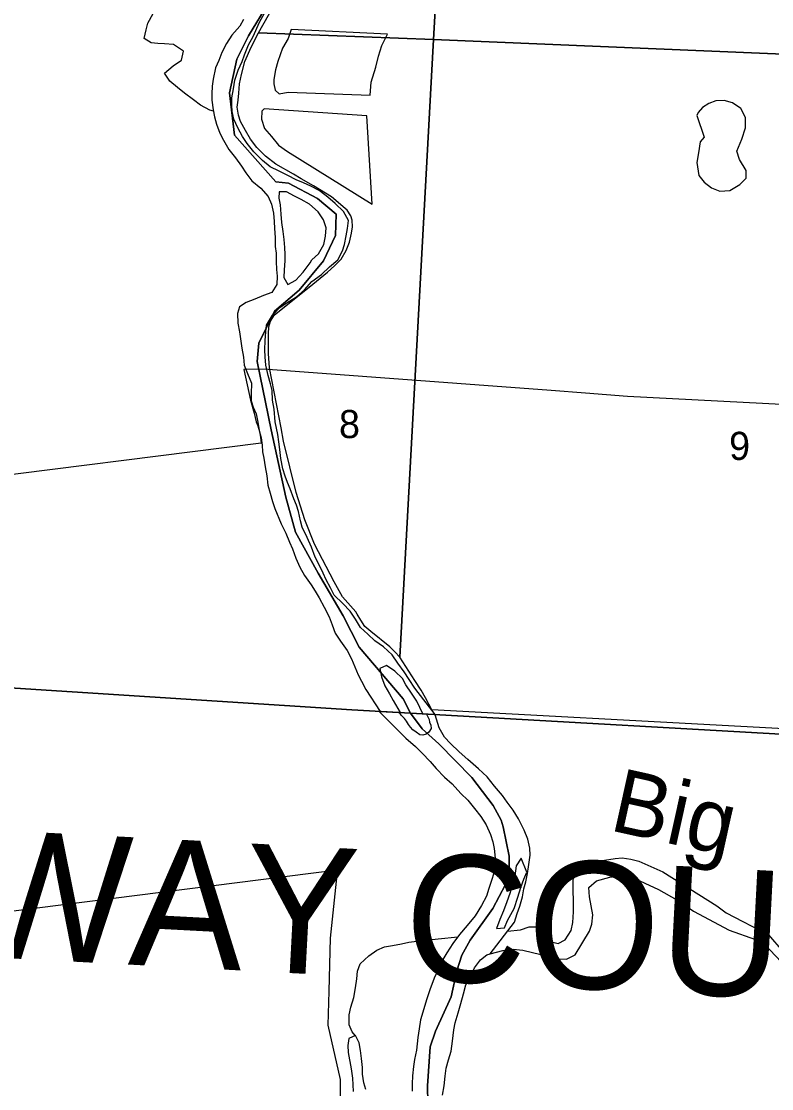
# Model space of a CAD drawing. Extents: x 114843 to 284848, y 317643 to 566895.
# Drawn here: x 199714 to 205606, y 326386 to 334768 of the extents above; entities that cross this region are included whole.
import ezdxf

# ---------------------------------------------------------------- set-up
doc = ezdxf.new("R2010")
doc.units = 0
for name, color, linetype in [('GM_X_Corporation', 7, 'Continuous'), ('GM_X_County', 7, 'Continuous'), ('GM_X_County_Text', 7, 'Continuous'), ('GM_X_Major_River', 7, 'Continuous'), ('GM_X_Major_River_Text', 7, 'Continuous'), ('GM_X_Minor_Lake', 7, 'Continuous'), ('GM_X_Minor_River', 7, 'Continuous'), ('GM_X_Section', 7, 'Continuous'), ('GM_X_Section_Text', 7, 'Continuous'), ('GM_X_Township', 7, 'Continuous')]:
    doc.layers.add(name, color=color, linetype=linetype)

msp = doc.modelspace()

# ---------------------------------------------------------------- linework, layer by layer
at = {"layer": 'GM_X_Corporation'}
for points in [[(206644.7, 331708.2), (204474.5, 331822.7), (204143.4, 331847.9), (203874.5, 331868.4), (201650.8, 332033.4), (201477, 332036.8), (201459.8, 332033.6), (201514.5, 331793.1), (201542.2, 331690.1), (201549, 331656.5), (201558.7, 331623.7), (201571.1, 331591.7), (201584.4, 331547.6), (201592.9, 331502.4), (201596.7, 331456.5), (199148, 331145.7)], [(198057.5, 327582), (202194, 328104.1), (202192.1, 328065.1), (202137.8, 327567.4), (202127.6, 327150.8), (202119.3, 326884.1), (202218.1, 326458.1), (202215.1, 326147.7)]]:
    msp.add_lwpolyline(points, dxfattribs=at)
at = {"layer": 'GM_X_County'}
for points in [[(234341.9, 327550.6), (226717.6, 328003.9), (223790.5, 328228.4), (218560.3, 328475.9), (218545.2, 328479.5), (213224.9, 328764.7), (208151.1, 329070.4), (208095.2, 329072.5), (206186.9, 329142.4), (202769.6, 329336.1), (202309.8, 329362.2), (198524.2, 329604), (197723.9, 329650.3), (193707.8, 329789.4), (193407.6, 329798.8), (192869.2, 329809.1), (189197.4, 329916.7), (185190.3, 330011.9), (181070.3, 330252.9), (177726, 330436.1)], [(177726, 330436.1), (181070.3, 330252.9), (185190.3, 330011.9), (189197.4, 329916.7), (192869.2, 329809.1), (193407.6, 329798.8), (193707.8, 329789.4), (197723.9, 329650.3), (198524.2, 329604), (202309.8, 329362.2), (202769.6, 329336.1), (206186.9, 329142.4), (208095.2, 329072.5), (208151.1, 329070.4), (213224.9, 328764.7), (218545.2, 328479.5), (218560.3, 328475.9), (223790.5, 328228.4), (226717.6, 328003.9), (234341.9, 327550.6)]]:
    msp.add_lwpolyline(points, dxfattribs=at)
at = {"layer": 'GM_X_Major_River'}
for p, q in [((202684.1, 329340.1), (202523.2, 329348.3)), ((202531.3, 329348), (202964.2, 329323.3)), ((202689.8, 329339.9), (202866.6, 329330.1)), ((202963.4, 329323.2), (202894.9, 329326.6))]:
    msp.add_line(p, q, dxfattribs=at)
for points in [[(201458.7, 334782.7), (201428.7, 334730.5), (201366.8, 334660.2), (201324.9, 334594), (201289, 334523.8), (201265.1, 334459.6), (201239.1, 334403.4), (201221.3, 334313.1), (201213.4, 334259), (201209.5, 334198.8), (201209.5, 334148.7), (201219.7, 334072.5), (201229.8, 334018.4), (201245.9, 333960.3), (201272, 333890.2), (201300.1, 333834.1), (201344.3, 333762), (201396.4, 333695.9), (201442.6, 333631.9), (201476.7, 333577.8), (201524.8, 333515.8), (201595, 333457.8), (201653.1, 333393.7), (201677.2, 333331.6), (201693.4, 333261.5), (201699.5, 333195.3), (201701.6, 333141.2), (201705.7, 333071), (201707.8, 332998.8), (201713.9, 332948.7), (201716, 332882.6), (201718.1, 332818.4), (201722.2, 332766.3), (201720.3, 332702.1), (201680.4, 332637.9), (201616.4, 332615.7), (201548.4, 332585.5), (201480.4, 332561.3), (201426.4, 332525.1), (201410.5, 332474.9), (201412.6, 332398.7), (201426.7, 332330.6), (201434.8, 332274.5), (201444.9, 332200.3), (201457.1, 332130.2), (201463.2, 332068), (201489.3, 332001.9), (201521.5, 331925.8), (201519.6, 331843.6), (201519.7, 331787.4), (201533.8, 331737.3), (201557.9, 331685.2), (201572, 331621.1), (201582.1, 331555), (201596.2, 331496.9), (201604.3, 331440.7), (201608.4, 331388.6), (201618.5, 331338.5), (201628.6, 331270.4), (201640.7, 331198.2), (201648.9, 331126), (201669, 331063.9), (201685.1, 330997.8), (201705.2, 330941.7), (201753.4, 330821.5), (201789.6, 330747.4), (201819.7, 330677.3), (201843.8, 330625.2), (201870, 330551.1), (201900.1, 330480.9), (201938.2, 330416.9), (201990.4, 330342.8), (202020.5, 330292.7), (202052.6, 330240.7), (202090.8, 330168.6), (202130.9, 330092.5), (202155, 330028.3), (202177.2, 329962.2), (202221.3, 329900.2), (202273.5, 329826.1), (202305.6, 329762), (202331.7, 329699.9), (202359.8, 329635.8), (202383.9, 329585.7), (202418.1, 329519.6), (202531.3, 329348)], [(202804.3, 329532.4), (202760.2, 329600.5), (202720, 329660.6), (202669.9, 329726.6), (202625.8, 329792.7), (202557.6, 329856.7), (202489.5, 329902.7), (202435.4, 329956.7), (202377.2, 330008.7), (202337.1, 330072.8), (202297, 330134.9), (202238.8, 330196.9), (202170.7, 330262.9), (202140.5, 330319), (202108.4, 330381.1), (202084.3, 330435.2), (202058.2, 330489.3), (202022.1, 330561.4), (201991.9, 330639.5), (201957.8, 330715.6), (201919.6, 330795.8), (201905.5, 330845.9), (201889.4, 330918), (201873.3, 330968.1), (201853.2, 331018.2), (201825, 331096.3), (201802.9, 331146.4), (201784.8, 331196.5), (201766.7, 331254.6), (201752.6, 331334.8), (201744.5, 331406.9), (201736.4, 331467.1), (201728.3, 331523.2), (201718.2, 331573.3), (201708.1, 331623.4), (201699.9, 331723.6), (201685.8, 331793.8), (201683.7, 331870), (201669.6, 331922.1), (201651.4, 331986.2), (201633.3, 332068.4), (201629.2, 332132.5), (201627.1, 332188.7), (201629, 332262.8), (201634.9, 332329), (201638.8, 332383.2), (201686.7, 332459.4), (201742.6, 332519.7), (201806.6, 332563.9), (201874.6, 332604.2), (201936.5, 332660.4), (201994.5, 332724.7), (202070.4, 332781), (202132.4, 332839.3), (202198.3, 332895.6), (202236.2, 332965.8), (202250.2, 333016), (202264.1, 333084.2), (202276, 333140.3), (202281.9, 333204.5), (202243.7, 333274.6), (202177.6, 333336.6), (202119.5, 333386.6), (202051.3, 333438.6), (201987.2, 333472.6), (201929.1, 333500.5), (201873.1, 333524.5), (201807, 333558.4), (201738.8, 333592.4), (201668.7, 333624.3), (201606.6, 333674.3), (201540.5, 333744.3), (201486.3, 333808.4), (201450.2, 333864.5), (201414.1, 333930.6), (201381.9, 333998.7), (201369.8, 334060.8), (201365.7, 334112.9), (201367.6, 334167), (201379.5, 334239.2), (201389.4, 334305.4), (201417.3, 334385.7), (201447.2, 334453.9), (201465.1, 334506.1), (201497, 334584.3), (201532.9, 334648.5), (201584.8, 334760.9), (201622.7, 334831.2)], [(201739.1, 333430), (201735.2, 333379.8), (201745.3, 333327.7), (201751.4, 333253.6), (201757.5, 333187.4), (201767.7, 333117.3), (201775.8, 333055.1), (201779.9, 332991), (201782, 332936.8), (201782.1, 332886.7), (201778.2, 332816.5), (201776.3, 332756.4), (201806.4, 332702.3), (201870.4, 332734.5), (201926.3, 332798.8), (201982.2, 332871.1)], [(201982.2, 332871.1), (201996.2, 332895.1), (202048.1, 332943.4), (202088.1, 333015.6), (202101.9, 333081.8), (202107.8, 333146), (202087.7, 333210.1), (202045.6, 333272.2), (201975.4, 333332.2), (201911.3, 333370.2), (201859.3, 333394.1), (201797.2, 333428.1), (201739.1, 333430)], [(202866.6, 329330.1), (202820.5, 329428.2), (202778.4, 329492.3), (202734.2, 329558.3), (202708.1, 329608.4), (202648, 329664.4), (202581.9, 329708.4), (202529.9, 329686.3), (202542, 329620.1), (202568.1, 329550), (202604.3, 329487.9), (202634.4, 329433.9), (202689.8, 329339.9)], [(202964.2, 329323.3), (202804.3, 329532.4)], [(202523.2, 329348.3), (202669.3, 329201.1), (202732.3, 329137.9), (202809.4, 329073), (202862.2, 329021.8), (202925.3, 328954.6), (202970.1, 328901.2), (203037.2, 328832.2), (203098.1, 328779), (203165.2, 328703.9), (203220.1, 328652.7), (203273.1, 328587.4), (203322.1, 328524), (203365.2, 328458.6), (203398.4, 328380.9), (203417.3, 328325.1), (203426.2, 328273.1), (203433.5, 328195), (203434.3, 328142.8), (203425.4, 328078.5), (203406.3, 328020), (203385.4, 327957.5), (203366.3, 327899), (203327.6, 327824.1), (203276.9, 327743), (203214.2, 327667.8), (203155.4, 327596.6), (203102.6, 327525.5), (203055.8, 327452.5), (203016.9, 327387.7), (202991.8, 327331.1), (202955.1, 327254.3), (202922.6, 327161.5), (202897.8, 327090.9), (202848.6, 326925.6), (202837.7, 326855.2), (202826.8, 326786.8), (202816.4, 326688.4), (202801.7, 326613.9), (202794.6, 326559.6), (202785.8, 326487.3), (202782.8, 326425.1), (202781.7, 326366.9)], [(202894.9, 329326.6), (202915.8, 329285.4), (202920.2, 329263.5), (202930.5, 329241.6), (202933, 329213.5), (202913.5, 329187.1), (202893.7, 329170.7), (202865.9, 329162.2), (202843.8, 329165.9), (202815.5, 329185.5), (202789.2, 329205.1), (202770.9, 329224.8), (202754.6, 329246.6), (202738.1, 329272.4), (202723.8, 329294.3), (202697.4, 329319.9), (202684.1, 329340.1)], [(203394.2, 327445.7), (203587.6, 327694.1), (203608.5, 327760.6), (203627.5, 327819.1), (203648.3, 327891.7), (203659.3, 327956), (203676.4, 328010.5), (203689.3, 328074.9), (203696.4, 328129.2), (203708.9, 328219.6), (203706, 328275.7), (203690.9, 328345.7), (203663.7, 328415.4), (203618.3, 328504.9), (203575.2, 328572.4), (203530.2, 328635.8), (203493.4, 328687.4), (203430.2, 328760.5), (203371, 328835.8), (203304, 328898.8), (203218.8, 328971.6), (203151.9, 329030.7), (203084.9, 329095.7), (203038, 329147.1), (202994.9, 329218.6), (202963.4, 329323.2)], [(203581.2, 328023.9), (203549.9, 327920.1), (203527, 327853.5), (203500.2, 327782.9), (203471.3, 327714.2), (203444.5, 327643.6), (203508.4, 327648.7), (203531.4, 327707.2), (203583.8, 327802.3), (203612.4, 327889.1), (203635.1, 327965.7), (203660, 328030.3), (203683.1, 328086.8), (203639, 328195.9)], [(203531.7, 327622.3), (203634.6, 327632.7), (203702.2, 327655.9), (203770.1, 327657.1), (203820.8, 327613.8), (203878, 327540.5), (203930.2, 327525.4), (203983.7, 327554.4), (204030.4, 327629.3), (204043.4, 327691.7), (204050, 327776.1), (204047.9, 328028.8), (204078.7, 328099.5), (204133.9, 328144.5), (204191.6, 328165.6), (204377, 328194.8), (204430.9, 328197.7), (204501, 328188.8), (204563.3, 328171.8), (204752.6, 328088.8), (205176.7, 327823.1), (205249.6, 327768.2), (205580.3, 327593.2), (205694.4, 327462.8)], [(203639, 328195.9), (203600.3, 328135.6), (203589.6, 328057.2), (203581.2, 328023.9)], [(203394.2, 327445.7), (203495.3, 327471.9), (203577.1, 327481.3), (203651.2, 327472.5), (203934.2, 327405.1), (203994.2, 327402.1), (204063.6, 327437.4), (204174.5, 327621.7), (204193.6, 327678.2), (204202.4, 327750.6), (204176.1, 327892.5), (204170.8, 327966.6), (204230, 328017.8), (204335.4, 328047.6), (204447.1, 328063.6), (204503.3, 328050.5), (204716.9, 327949.8), (204860.1, 327869.9), (204993.5, 327779.9), (205271.8, 327630.1), (205478.9, 327557.4), (205547.5, 327522.5), (205728.5, 327333)], [(203022.2, 326334.8), (203033, 326407.2), (203041.7, 326483.6), (203050.6, 326547.9), (203067.6, 326612.4), (203088.4, 326680.9), (203099.1, 326759.3), (203109.7, 326847.7), (203120.8, 326904.1), (203143.5, 326980.7), (203166.3, 327055.2), (203185, 327131.8), (203203.9, 327200.3), (203246.6, 327279.2), (203273.6, 327335.8), (203318.6, 327396.8), (203369.9, 327437.7), (203394.2, 327445.7)], [(202419.7, 326378.9), (202402.8, 326432.7), (202393.7, 326500.8), (202392.9, 326552.9), (202385.7, 326623), (202376.7, 326687), (202367.7, 326747), (202336.8, 326804.7), (202285.2, 326779.7), (202278.1, 326725.4), (202281, 326669.4)], [(202281, 326669.4), (202303.1, 326541.4), (202314.3, 326469.4), (202317.1, 326417.3), (202320, 326363.2)]]:
    msp.add_lwpolyline(points, dxfattribs=at)
at = {"layer": 'GM_X_Minor_Lake'}
for points in [[(202454.1, 334189.2), (202460.3, 334291.4), (202498.5, 334409.6), (202518.6, 334493.8), (202544.8, 334578), (202589, 334668.1), (201832.5, 334705.2), (201808.4, 334633.1), (201764.2, 334557), (201728, 334452.8), (201709.9, 334386.6), (201697.8, 334312.5), (201697.7, 334276.4), (201707.6, 334228.3), (201739.6, 334200.1), (201809.7, 334212.1)], [(201809.7, 334212.1), (202454.1, 334189.2)], [(205075.4, 333858.9), (205045.3, 333822.8), (205031.2, 333736.6), (205019.1, 333658.4), (205032.9, 333558.2), (205074.9, 333506), (205132.8, 333461.8), (205198.8, 333433.6), (205278.9, 333439.5), (205355, 333487.6), (205407.1, 333537.6), (205405.2, 333597.8), (205353.3, 333684.1), (205333.4, 333748.2), (205371.6, 333842.4), (205401.8, 333932.6), (205399.9, 334012.8), (205364, 334083), (205298, 334127.2), (205234, 334145.3), (205167.9, 334143.4), (205111.9, 334123.5), (205063.8, 334091.4), (205027.7, 334051.4), (205017.7, 334029.4)], [(202425.8, 334026.8), (201619.4, 334080), (201603.3, 334062), (201599.2, 333999.8), (201623.1, 333927.6), (201677, 333863.4), (201733, 333795.2), (201802.9, 333745), (202468.8, 333333.1)], [(202468.8, 333333.1), (202425.8, 334026.8)], [(205017.7, 334029.4), (205075.4, 333858.9)]]:
    msp.add_lwpolyline(points, dxfattribs=at)
at = {"layer": 'GM_X_Minor_River'}
for points in [[(201221.6, 334062.1), (201193, 334070.6), (201121, 334110.7), (201065.1, 334150.9), (200995.1, 334203.1), (200941.1, 334249.3), (200879.2, 334299.5), (200837.2, 334361.7), (200905.4, 334417.8), (200971.5, 334463.8), (200987.6, 334533.9), (200909.6, 334586.2), (200837.6, 334592.3), (200785.6, 334594.4), (200733.5, 334598.4), (200677.6, 334634.6), (200693.7, 334700.7), (200705.8, 334752.8), (200749.9, 334831)], [(202334.4, 326803.5), (202312.3, 326832.3), (202289.4, 326888.1), (202288.1, 326966.3), (202301.2, 327026.7), (202323.9, 327103.3), (202336.7, 327177.7), (202347.5, 327248.1), (202352.5, 327308.3), (202375.5, 327366.9), (202442.5, 327430.2), (202505.7, 327473.4), (202565.3, 327500.4), (202629, 327511.5), (202698.8, 327524.7), (202756.6, 327535.7), (202858.3, 327549.5), (202914.2, 327554.4), (202986.1, 327561.7), (203141, 327577.2)]]:
    msp.add_lwpolyline(points, dxfattribs=at)
at = {"layer": 'GM_X_Section'}
msp.add_lwpolyline([(208485.6, 339850.8), (208132.8, 334409.4), (202949.2, 334626.4), (203055.3, 336458.7)], dxfattribs=at)
for points in [[(203055.3, 336458.7), (202949.2, 334626.4), (201575, 334677), (201698.8, 334895.2), (201796.6, 335055.3), (201836.6, 335125.3), (201902.5, 335249.4), (201996.3, 335431.5), (202052.2, 335533.6), (202098.1, 335589.7), (202140.1, 335643.7), (202228, 335721.8), (202355.9, 335824), (202501.8, 335926.1), (202701.7, 336066.3), (202761.7, 336106.4), (202829.6, 336160.5), (202905.5, 336238.6), (202945.5, 336290.6), (202973.5, 336328.6)], [(202949.2, 334626.4), (202686, 329773.7), (202648, 329815.6), (202608, 329855.6), (202457.8, 329975.5), (202411.8, 330015.4), (202379.7, 330065.4), (202351.7, 330113.4), (202339.7, 330131.4), (202235.5, 330249.3), (202171.4, 330365.2), (202015.1, 330661.1), (201938.9, 330853), (201870.7, 331069), (201772.3, 331470.9), (201754.2, 331574.9), (201663.7, 332046.9), (201655.6, 332160.9), (201653.4, 332314.9), (201657.4, 332368.9), (201669.3, 332412.9), (201701.2, 332462.9), (201855.1, 332587.1), (201975.1, 332681.2), (202116.9, 332799.4), (202172.9, 332847.4), (202224.9, 332901.5), (202264.8, 332967.6), (202290.7, 333033.6), (202306.7, 333105.6), (202314.6, 333153.6), (202312.5, 333207.6), (202300.5, 333239.6), (202272.5, 333285.6), (202256.4, 333299.6), (202150.3, 333389.5), (202008.2, 333477.4), (201912.2, 333531.3), (201852.2, 333567.2), (201712.1, 333647.1), (201632, 333709), (201563.9, 333776.9), (201513.8, 333842.9), (201473.8, 333910.8), (201435.7, 333980.8), (201419.6, 334030.8), (201409.6, 334094.8), (201415.5, 334148.8), (201421.5, 334204.8), (201427.4, 334276.9), (201441.3, 334350.9), (201469.2, 334452.9), (201519.1, 334565), (201575, 334677)], [(202949.2, 334626.4), (208132.8, 334409.4), (207789.5, 329099.8), (202938, 329360.9), (202888.4, 329455.9), (202854.3, 329515.8), (202804.2, 329591.8), (202686, 329773.7)]]:
    msp.add_lwpolyline(points, close=True, dxfattribs=at)
at = {"layer": 'GM_X_Township'}
for points in [[(201657.8, 334916.5), (201496.5, 334653.5), (201406.3, 334471.4), (201349.2, 334206), (201386.8, 333874.8), (201711, 333506.8), (201812.8, 333497.4), (202040.6, 333378), (202185.9, 333254.3), (202180.7, 333086.7), (202087, 332886.2), (201894.9, 332656.3), (201702, 332491.5), (201578.9, 332240.8), (201565.5, 332096.3), (201674.4, 331560.4), (201791.4, 331030.9), (201866.4, 330755.3), (202043.4, 330433.7), (202240, 330099.3), (202366.7, 329852.3), (202713.4, 329446.9), (202769.6, 329336.1), (202309.8, 329362.2), (198524.2, 329604)], [(206186.9, 329142.4), (202769.6, 329336.1), (202713.4, 329446.9), (202366.7, 329852.3), (202240, 330099.3), (202043.4, 330433.7), (201866.4, 330755.3), (201791.4, 331030.9), (201674.4, 331560.4), (201565.5, 332096.3), (201578.9, 332240.8), (201702, 332491.5), (201894.9, 332656.3), (202087, 332886.2), (202180.7, 333086.7), (202185.9, 333254.3), (202040.6, 333378), (201812.8, 333497.4), (201711, 333506.8), (201386.8, 333874.8), (201349.2, 334206), (201406.3, 334471.4), (201496.5, 334653.5), (201657.8, 334916.5)], [(198524.2, 329604), (202309.8, 329362.2), (202769.6, 329336.1), (202862.3, 329211.9), (202992.1, 329093.7), (203250.3, 328829.3), (203419.9, 328609.5), (203481.7, 328494.2), (203498.6, 328442.3), (203544.3, 328212.4), (203544.2, 328098.1), (203516, 327989.3), (203415.1, 327801.1), (203239.3, 327551.4), (203173.2, 327434), (203133.3, 327311), (203088.7, 327107.6), (202965.1, 326836.8), (202925.2, 326713.8), (202904.2, 326408.6), (202908.7, 326135.9)], [(202908.7, 326135.9), (202904.2, 326408.6), (202925.2, 326713.8), (202965.1, 326836.8), (203088.7, 327107.6), (203133.3, 327311), (203173.2, 327434), (203239.3, 327551.4), (203415.1, 327801.1), (203516, 327989.3), (203544.2, 328098.1), (203544.3, 328212.4), (203498.6, 328442.3), (203481.7, 328494.2), (203419.9, 328609.5), (203250.3, 328829.3), (202992.1, 329093.7), (202862.3, 329211.9), (202769.6, 329336.1), (206186.9, 329142.4), (208095.2, 329072.5), (208151.1, 329070.4), (213224.9, 328764.7), (218545.2, 328479.5)]]:
    msp.add_lwpolyline(points, dxfattribs=at)

# ---------------------------------------------------------------- texts
at = {"layer": 'GM_X_County_Text'}
msp.add_text('PICKAWAY COUNTY', height=1000.08, rotation=356.99519, dxfattribs=at).set_placement((195279.2, 327637.7))
at = {"layer": 'GM_X_Major_River_Text'}
msp.add_text('Big', height=500.02, rotation=347.52627, dxfattribs=at).set_placement((204321, 328417.9))
at = {"layer": 'GM_X_Section_Text'}
for s, rotation, p in [('8', 0.41323, (202209, 331494.6)), ('9', 0.41329, (205273, 331323.1))]:
    msp.add_text(s, height=221, rotation=rotation, dxfattribs=at).set_placement(p)

doc.saveas('drawing.dxf')
